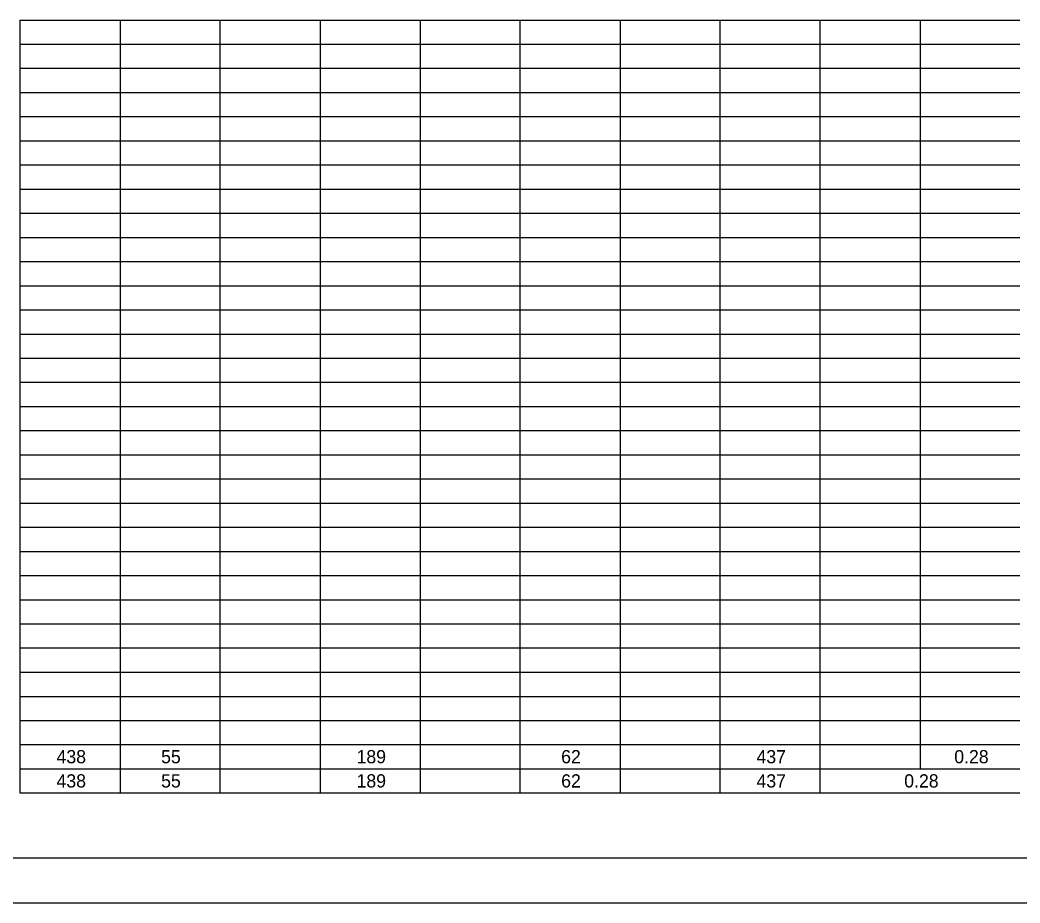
# Model space of a CAD drawing. Extents: x 0 to 34, y 0 to 22.
# Drawn here: x 14.09 to 25.28, y 0 to 9.88 of the extents above; entities that cross this region are included whole.
import ezdxf

# ---------------------------------------------------------------- set-up
doc = ezdxf.new("R2010")
doc.units = 0
for name, color, linetype in [('SH_Border', 7, 'Continuous'), ('SH_Cut_Line', 7, 'Continuous'), ('SH_Data', 7, 'Continuous')]:
    doc.layers.add(name, color=color, linetype=linetype)

msp = doc.modelspace()

# ---------------------------------------------------------------- linework, layer by layer
at = {"layer": 'SH_Border'}
msp.add_lwpolyline([(1.5, 21.5), (33.5, 21.5), (33.5, 0.5), (1.5, 0.5)], close=True, dxfattribs=at)
at = {"layer": 'SH_Cut_Line'}
msp.add_lwpolyline([(0, 0), (34, 0), (34, 22), (0, 22)], close=True, dxfattribs=at)
at = {"layer": 'SH_Data'}
for p, q in [((14.086, 9.879), (15.206, 9.879)), ((14.086, 9.879), (14.086, 9.609)), ((15.206, 9.879), (16.325, 9.879)), ((15.206, 9.879), (15.206, 9.609)), ((16.325, 9.879), (24.163, 9.879)), ((16.325, 9.879), (16.325, 9.609)), ((17.445, 9.879), (17.445, 9.609)), ((18.565, 9.879), (18.565, 9.609)), ((19.684, 9.879), (19.684, 9.609)), ((20.804, 9.879), (20.804, 9.609)), ((21.923, 9.879), (21.923, 9.609)), ((23.043, 9.879), (23.043, 9.609)), ((24.163, 9.879), (25.282, 9.879)), ((24.163, 9.879), (24.163, 9.609)), ((14.086, 9.609), (15.206, 9.609)), ((14.086, 9.609), (14.086, 9.339)), ((15.206, 9.609), (16.325, 9.609)), ((15.206, 9.609), (15.206, 9.339)), ((16.325, 9.609), (24.163, 9.609)), ((16.325, 9.609), (16.325, 9.339)), ((17.445, 9.609), (17.445, 9.339)), ((18.565, 9.609), (18.565, 9.339)), ((19.684, 9.609), (19.684, 9.339)), ((20.804, 9.609), (20.804, 9.339)), ((21.923, 9.609), (21.923, 9.339)), ((23.043, 9.609), (23.043, 9.339)), ((24.163, 9.609), (25.282, 9.609)), ((24.163, 9.609), (24.163, 9.339)), ((14.086, 9.339), (15.206, 9.339)), ((14.086, 9.339), (14.086, 9.069)), ((15.206, 9.339), (16.325, 9.339)), ((15.206, 9.339), (15.206, 9.069)), ((16.325, 9.339), (24.163, 9.339)), ((16.325, 9.339), (16.325, 9.069)), ((17.445, 9.339), (17.445, 9.069)), ((18.565, 9.339), (18.565, 9.069)), ((19.684, 9.339), (19.684, 9.069)), ((20.804, 9.339), (20.804, 9.069)), ((21.923, 9.339), (21.923, 9.069)), ((23.043, 9.339), (23.043, 9.069)), ((24.163, 9.339), (25.282, 9.339)), ((24.163, 9.339), (24.163, 9.069)), ((14.086, 9.069), (15.206, 9.069)), ((14.086, 9.069), (14.086, 8.798)), ((15.206, 9.069), (16.325, 9.069)), ((15.206, 9.069), (15.206, 8.798)), ((16.325, 9.069), (24.163, 9.069)), ((16.325, 9.069), (16.325, 8.798)), ((17.445, 9.069), (17.445, 8.798)), ((18.565, 9.069), (18.565, 8.798)), ((19.684, 9.069), (19.684, 8.798)), ((20.804, 9.069), (20.804, 8.798)), ((21.923, 9.069), (21.923, 8.798)), ((23.043, 9.069), (23.043, 8.798)), ((24.163, 9.069), (25.282, 9.069)), ((24.163, 9.069), (24.163, 8.798)), ((14.086, 8.798), (15.206, 8.798)), ((14.086, 8.798), (14.086, 8.528)), ((15.206, 8.798), (16.325, 8.798)), ((15.206, 8.798), (15.206, 8.528)), ((16.325, 8.798), (24.163, 8.798)), ((16.325, 8.798), (16.325, 8.528)), ((17.445, 8.798), (17.445, 8.528)), ((18.565, 8.798), (18.565, 8.528)), ((19.684, 8.798), (19.684, 8.528)), ((20.804, 8.798), (20.804, 8.528)), ((21.923, 8.798), (21.923, 8.528)), ((23.043, 8.798), (23.043, 8.528)), ((24.163, 8.798), (25.282, 8.798)), ((24.163, 8.798), (24.163, 8.528)), ((14.086, 8.528), (15.206, 8.528)), ((14.086, 8.528), (14.086, 8.258)), ((15.206, 8.528), (16.325, 8.528)), ((15.206, 8.528), (15.206, 8.258)), ((16.325, 8.528), (24.163, 8.528)), ((16.325, 8.528), (16.325, 8.258)), ((17.445, 8.528), (17.445, 8.258)), ((18.565, 8.528), (18.565, 8.258)), ((19.684, 8.528), (19.684, 8.258)), ((20.804, 8.528), (20.804, 8.258)), ((21.923, 8.528), (21.923, 8.258)), ((23.043, 8.528), (23.043, 8.258)), ((24.163, 8.528), (25.282, 8.528)), ((24.163, 8.528), (24.163, 8.258)), ((14.086, 8.258), (15.206, 8.258)), ((14.086, 8.258), (14.086, 7.988)), ((15.206, 8.258), (16.325, 8.258)), ((15.206, 8.258), (15.206, 7.988)), ((16.325, 8.258), (24.163, 8.258)), ((16.325, 8.258), (16.325, 7.988)), ((17.445, 8.258), (17.445, 7.988)), ((18.565, 8.258), (18.565, 7.988)), ((19.684, 8.258), (19.684, 7.988)), ((20.804, 8.258), (20.804, 7.988)), ((21.923, 8.258), (21.923, 7.988)), ((23.043, 8.258), (23.043, 7.988)), ((24.163, 8.258), (25.282, 8.258)), ((24.163, 8.258), (24.163, 7.988)), ((14.086, 7.988), (15.206, 7.988)), ((14.086, 7.988), (14.086, 7.717)), ((15.206, 7.988), (16.325, 7.988)), ((15.206, 7.988), (15.206, 7.717)), ((16.325, 7.988), (24.163, 7.988)), ((16.325, 7.988), (16.325, 7.717)), ((17.445, 7.988), (17.445, 7.717)), ((18.565, 7.988), (18.565, 7.717)), ((19.684, 7.988), (19.684, 7.717)), ((20.804, 7.988), (20.804, 7.717)), ((21.923, 7.988), (21.923, 7.717)), ((23.043, 7.988), (23.043, 7.717)), ((24.163, 7.988), (25.282, 7.988)), ((24.163, 7.988), (24.163, 7.717)), ((14.086, 7.717), (15.206, 7.717)), ((14.086, 7.717), (14.086, 7.447)), ((15.206, 7.717), (16.325, 7.717)), ((15.206, 7.717), (15.206, 7.447)), ((16.325, 7.717), (24.163, 7.717)), ((16.325, 7.717), (16.325, 7.447)), ((17.445, 7.717), (17.445, 7.447)), ((18.565, 7.717), (18.565, 7.447)), ((19.684, 7.717), (19.684, 7.447)), ((20.804, 7.717), (20.804, 7.447)), ((21.923, 7.717), (21.923, 7.447)), ((23.043, 7.717), (23.043, 7.447)), ((24.163, 7.717), (25.282, 7.717)), ((24.163, 7.717), (24.163, 7.447)), ((14.086, 7.447), (15.206, 7.447)), ((14.086, 7.447), (14.086, 7.177)), ((15.206, 7.447), (16.325, 7.447)), ((15.206, 7.447), (15.206, 7.177)), ((16.325, 7.447), (24.163, 7.447)), ((16.325, 7.447), (16.325, 7.177)), ((17.445, 7.447), (17.445, 7.177)), ((18.565, 7.447), (18.565, 7.177)), ((19.684, 7.447), (19.684, 7.177)), ((20.804, 7.447), (20.804, 7.177)), ((21.923, 7.447), (21.923, 7.177)), ((23.043, 7.447), (23.043, 7.177)), ((24.163, 7.447), (25.282, 7.447)), ((24.163, 7.447), (24.163, 7.177)), ((14.086, 7.177), (15.206, 7.177)), ((14.086, 7.177), (14.086, 6.907)), ((15.206, 7.177), (16.325, 7.177)), ((15.206, 7.177), (15.206, 6.907)), ((16.325, 7.177), (24.163, 7.177)), ((16.325, 7.177), (16.325, 6.907)), ((17.445, 7.177), (17.445, 6.907)), ((18.565, 7.177), (18.565, 6.907)), ((19.684, 7.177), (19.684, 6.907)), ((20.804, 7.177), (20.804, 6.907)), ((21.923, 7.177), (21.923, 6.907)), ((23.043, 7.177), (23.043, 6.907)), ((24.163, 7.177), (25.282, 7.177)), ((24.163, 7.177), (24.163, 6.907)), ((14.086, 6.907), (15.206, 6.907)), ((14.086, 6.907), (14.086, 6.636)), ((15.206, 6.907), (16.325, 6.907)), ((15.206, 6.907), (15.206, 6.636)), ((16.325, 6.907), (24.163, 6.907)), ((16.325, 6.907), (16.325, 6.636)), ((17.445, 6.907), (17.445, 6.636)), ((18.565, 6.907), (18.565, 6.636)), ((19.684, 6.907), (19.684, 6.636)), ((20.804, 6.907), (20.804, 6.636)), ((21.923, 6.907), (21.923, 6.636)), ((23.043, 6.907), (23.043, 6.636)), ((24.163, 6.907), (25.282, 6.907)), ((24.163, 6.907), (24.163, 6.636)), ((14.086, 6.636), (15.206, 6.636)), ((14.086, 6.636), (14.086, 6.366)), ((15.206, 6.636), (16.325, 6.636)), ((15.206, 6.636), (15.206, 6.366)), ((16.325, 6.636), (24.163, 6.636)), ((16.325, 6.636), (16.325, 6.366)), ((17.445, 6.636), (17.445, 6.366)), ((18.565, 6.636), (18.565, 6.366)), ((19.684, 6.636), (19.684, 6.366)), ((20.804, 6.636), (20.804, 6.366)), ((21.923, 6.636), (21.923, 6.366)), ((23.043, 6.636), (23.043, 6.366)), ((24.163, 6.636), (25.282, 6.636)), ((24.163, 6.636), (24.163, 6.366)), ((14.086, 6.366), (15.206, 6.366)), ((14.086, 6.366), (14.086, 5.826)), ((15.206, 6.366), (16.325, 6.366)), ((15.206, 6.366), (15.206, 5.826)), ((16.325, 6.366), (24.163, 6.366)), ((16.325, 6.366), (16.325, 5.826)), ((17.445, 6.366), (17.445, 5.826)), ((18.565, 6.366), (18.565, 5.826)), ((19.684, 6.366), (19.684, 5.826)), ((20.804, 6.366), (20.804, 5.826)), ((21.923, 6.366), (21.923, 5.826)), ((23.043, 6.366), (23.043, 5.826)), ((24.163, 6.366), (25.282, 6.366)), ((24.163, 6.366), (24.163, 5.826)), ((14.086, 6.096), (15.206, 6.096)), ((15.206, 6.096), (16.325, 6.096)), ((16.325, 6.096), (24.163, 6.096)), ((24.163, 6.096), (25.282, 6.096)), ((14.086, 5.826), (15.206, 5.826)), ((14.086, 5.826), (14.086, 5.555)), ((15.206, 5.826), (16.325, 5.826)), ((15.206, 5.826), (15.206, 5.555)), ((16.325, 5.826), (24.163, 5.826)), ((16.325, 5.826), (16.325, 5.555)), ((17.445, 5.826), (17.445, 5.555)), ((18.565, 5.826), (18.565, 5.555)), ((19.684, 5.826), (19.684, 5.555)), ((20.804, 5.826), (20.804, 5.555)), ((21.923, 5.826), (21.923, 5.555)), ((23.043, 5.826), (23.043, 5.555)), ((24.163, 5.826), (25.282, 5.826)), ((24.163, 5.826), (24.163, 5.555)), ((14.086, 5.555), (15.206, 5.555)), ((14.086, 5.555), (14.086, 5.285)), ((15.206, 5.555), (16.325, 5.555)), ((15.206, 5.555), (15.206, 5.285)), ((16.325, 5.555), (24.163, 5.555)), ((16.325, 5.555), (16.325, 5.285)), ((17.445, 5.555), (17.445, 5.285)), ((18.565, 5.555), (18.565, 5.285)), ((19.684, 5.555), (19.684, 5.285)), ((20.804, 5.555), (20.804, 5.285)), ((21.923, 5.555), (21.923, 5.285)), ((23.043, 5.555), (23.043, 5.285)), ((24.163, 5.555), (25.282, 5.555)), ((24.163, 5.555), (24.163, 5.285)), ((14.086, 5.285), (15.206, 5.285)), ((14.086, 5.285), (14.086, 5.015)), ((15.206, 5.285), (16.325, 5.285)), ((15.206, 5.285), (15.206, 5.015)), ((16.325, 5.285), (24.163, 5.285)), ((16.325, 5.285), (16.325, 5.015)), ((17.445, 5.285), (17.445, 5.015)), ((18.565, 5.285), (18.565, 5.015)), ((19.684, 5.285), (19.684, 5.015)), ((20.804, 5.285), (20.804, 5.015)), ((21.923, 5.285), (21.923, 5.015)), ((23.043, 5.285), (23.043, 5.015)), ((24.163, 5.285), (25.282, 5.285)), ((24.163, 5.285), (24.163, 5.015)), ((14.086, 5.015), (15.206, 5.015)), ((14.086, 5.015), (14.086, 4.474)), ((15.206, 5.015), (16.325, 5.015)), ((15.206, 5.015), (15.206, 4.474)), ((16.325, 5.015), (24.163, 5.015)), ((16.325, 5.015), (16.325, 4.474)), ((17.445, 5.015), (17.445, 4.474)), ((18.565, 5.015), (18.565, 4.474)), ((19.684, 5.015), (19.684, 4.474)), ((20.804, 5.015), (20.804, 4.474)), ((21.923, 5.015), (21.923, 4.474)), ((23.043, 5.015), (23.043, 4.474)), ((24.163, 5.015), (25.282, 5.015)), ((24.163, 5.015), (24.163, 4.474)), ((14.086, 4.745), (15.206, 4.745)), ((15.206, 4.745), (16.325, 4.745)), ((16.325, 4.745), (24.163, 4.745)), ((24.163, 4.745), (25.282, 4.745)), ((14.086, 4.474), (15.206, 4.474)), ((14.086, 4.474), (14.086, 4.204)), ((15.206, 4.474), (16.325, 4.474)), ((15.206, 4.474), (15.206, 4.204)), ((16.325, 4.474), (24.163, 4.474)), ((16.325, 4.474), (16.325, 4.204)), ((17.445, 4.474), (17.445, 4.204)), ((18.565, 4.474), (18.565, 4.204)), ((19.684, 4.474), (19.684, 4.204)), ((20.804, 4.474), (20.804, 4.204)), ((21.923, 4.474), (21.923, 4.204)), ((23.043, 4.474), (23.043, 4.204)), ((24.163, 4.474), (25.282, 4.474)), ((24.163, 4.474), (24.163, 4.204)), ((14.086, 4.204), (15.206, 4.204)), ((14.086, 4.204), (14.086, 3.934)), ((15.206, 4.204), (16.325, 4.204)), ((15.206, 4.204), (15.206, 3.934)), ((16.325, 4.204), (24.163, 4.204)), ((16.325, 4.204), (16.325, 3.934)), ((17.445, 4.204), (17.445, 3.934)), ((18.565, 4.204), (18.565, 3.934)), ((19.684, 4.204), (19.684, 3.934)), ((20.804, 4.204), (20.804, 3.934)), ((21.923, 4.204), (21.923, 3.934)), ((23.043, 4.204), (23.043, 3.934)), ((24.163, 4.204), (25.282, 4.204)), ((24.163, 4.204), (24.163, 3.934)), ((14.086, 3.934), (15.206, 3.934)), ((14.086, 3.934), (14.086, 3.664)), ((15.206, 3.934), (16.325, 3.934)), ((15.206, 3.934), (15.206, 3.664)), ((16.325, 3.934), (24.163, 3.934)), ((16.325, 3.934), (16.325, 3.664)), ((17.445, 3.934), (17.445, 3.664)), ((18.565, 3.934), (18.565, 3.664)), ((19.684, 3.934), (19.684, 3.664)), ((20.804, 3.934), (20.804, 3.664)), ((21.923, 3.934), (21.923, 3.664)), ((23.043, 3.934), (23.043, 3.664)), ((24.163, 3.934), (25.282, 3.934)), ((24.163, 3.934), (24.163, 3.664)), ((14.086, 3.664), (15.206, 3.664)), ((14.086, 3.664), (14.086, 3.123)), ((15.206, 3.664), (16.325, 3.664)), ((15.206, 3.664), (15.206, 3.123)), ((16.325, 3.664), (24.163, 3.664)), ((16.325, 3.664), (16.325, 3.123)), ((17.445, 3.664), (17.445, 3.123)), ((18.565, 3.664), (18.565, 3.123)), ((19.684, 3.664), (19.684, 3.123)), ((20.804, 3.664), (20.804, 3.123)), ((21.923, 3.664), (21.923, 3.123)), ((23.043, 3.664), (23.043, 3.123)), ((24.163, 3.664), (25.282, 3.664)), ((24.163, 3.664), (24.163, 3.123)), ((14.086, 3.393), (15.206, 3.393)), ((15.206, 3.393), (16.325, 3.393)), ((16.325, 3.393), (24.163, 3.393)), ((24.163, 3.393), (25.282, 3.393)), ((14.086, 3.123), (15.206, 3.123)), ((14.086, 3.123), (14.086, 2.853)), ((15.206, 3.123), (16.325, 3.123)), ((15.206, 3.123), (15.206, 2.853)), ((16.325, 3.123), (24.163, 3.123)), ((16.325, 3.123), (16.325, 2.853)), ((17.445, 3.123), (17.445, 2.853)), ((18.565, 3.123), (18.565, 2.853)), ((19.684, 3.123), (19.684, 2.853)), ((20.804, 3.123), (20.804, 2.853)), ((21.923, 3.123), (21.923, 2.853)), ((23.043, 3.123), (23.043, 2.853)), ((24.163, 3.123), (25.282, 3.123)), ((24.163, 3.123), (24.163, 2.853)), ((14.086, 2.853), (15.206, 2.853)), ((14.086, 2.853), (14.086, 2.583)), ((15.206, 2.853), (16.325, 2.853)), ((15.206, 2.853), (15.206, 2.583)), ((16.325, 2.853), (24.163, 2.853)), ((16.325, 2.853), (16.325, 2.583)), ((17.445, 2.853), (17.445, 2.583)), ((18.565, 2.853), (18.565, 2.583)), ((19.684, 2.853), (19.684, 2.583)), ((20.804, 2.853), (20.804, 2.583)), ((21.923, 2.853), (21.923, 2.583)), ((23.043, 2.853), (23.043, 2.583)), ((24.163, 2.853), (25.282, 2.853)), ((24.163, 2.853), (24.163, 2.583)), ((14.086, 2.583), (15.206, 2.583)), ((14.086, 2.583), (14.086, 2.312)), ((15.206, 2.583), (16.325, 2.583)), ((15.206, 2.583), (15.206, 2.312)), ((16.325, 2.583), (24.163, 2.583)), ((16.325, 2.583), (16.325, 2.312)), ((17.445, 2.583), (17.445, 2.312)), ((18.565, 2.583), (18.565, 2.312)), ((19.684, 2.583), (19.684, 2.312)), ((20.804, 2.583), (20.804, 2.312)), ((21.923, 2.583), (21.923, 2.312)), ((23.043, 2.583), (23.043, 2.312)), ((24.163, 2.583), (25.282, 2.583)), ((24.163, 2.583), (24.163, 2.312)), ((14.086, 2.312), (15.206, 2.312)), ((14.086, 2.312), (14.086, 1.772)), ((15.206, 2.312), (16.325, 2.312)), ((15.206, 2.312), (15.206, 1.772)), ((16.325, 2.312), (24.163, 2.312)), ((16.325, 2.312), (16.325, 1.772)), ((17.445, 2.312), (17.445, 1.772)), ((18.565, 2.312), (18.565, 1.772)), ((19.684, 2.312), (19.684, 1.772)), ((20.804, 2.312), (20.804, 1.772)), ((21.923, 2.312), (21.923, 1.772)), ((23.043, 2.312), (23.043, 1.772)), ((24.163, 2.312), (25.282, 2.312)), ((24.163, 2.312), (24.163, 1.772)), ((14.086, 2.042), (15.206, 2.042)), ((15.206, 2.042), (16.325, 2.042)), ((16.325, 2.042), (24.163, 2.042)), ((24.163, 2.042), (25.282, 2.042)), ((14.086, 1.772), (15.206, 1.772)), ((14.086, 1.772), (14.086, 1.502)), ((15.206, 1.772), (16.325, 1.772)), ((15.206, 1.772), (15.206, 1.502)), ((16.325, 1.772), (24.163, 1.772)), ((16.325, 1.772), (16.325, 1.502)), ((17.445, 1.772), (17.445, 1.502)), ((18.565, 1.772), (18.565, 1.502)), ((19.684, 1.772), (19.684, 1.502)), ((20.804, 1.772), (20.804, 1.502)), ((21.923, 1.772), (21.923, 1.502)), ((23.043, 1.772), (23.043, 1.502)), ((24.163, 1.772), (25.282, 1.772)), ((24.163, 1.772), (24.163, 1.502)), ((14.086, 1.502), (15.206, 1.502)), ((14.086, 1.502), (14.086, 1.231)), ((15.206, 1.502), (16.325, 1.502)), ((15.206, 1.502), (15.206, 1.231)), ((16.325, 1.502), (24.163, 1.502)), ((16.325, 1.502), (16.325, 1.231)), ((17.445, 1.502), (17.445, 1.231)), ((18.565, 1.502), (18.565, 1.231)), ((19.684, 1.502), (19.684, 1.231)), ((20.804, 1.502), (20.804, 1.231)), ((21.923, 1.502), (21.923, 1.231)), ((23.043, 1.502), (23.043, 1.231)), ((24.163, 1.502), (25.282, 1.502)), ((14.086, 1.231), (15.206, 1.231)), ((15.206, 1.231), (16.325, 1.231)), ((16.325, 1.231), (24.163, 1.231)), ((24.163, 1.231), (25.282, 1.231))]:
    msp.add_line(p, q, dxfattribs=at)

# ---------------------------------------------------------------- texts
for s, p in [('438', (14.495, 1.563)), ('55', (15.666, 1.563)), ('189', (17.854, 1.563)), ('62', (20.145, 1.563)), ('437', (22.332, 1.563)), ('0.28', (24.546, 1.563)), ('438', (14.495, 1.292)), ('55', (15.666, 1.292)), ('189', (17.854, 1.292)), ('62', (20.145, 1.292)), ('437', (22.332, 1.292)), ('0.28', (23.986, 1.292))]:
    msp.add_text(s, height=0.148, dxfattribs=at).set_placement(p)

doc.saveas('drawing.dxf')
